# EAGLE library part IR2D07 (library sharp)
16.bit LED panel driver Source: http://document.sharpsma.com/files/IR2D07.pdf
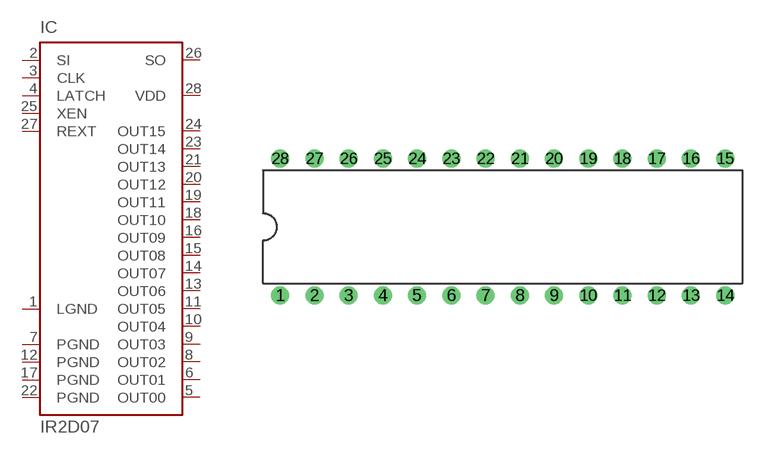
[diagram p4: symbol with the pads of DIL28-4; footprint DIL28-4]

Designator prefix IC

## IR2D07 (OC_FARNELL: unknown; OC_NEWARK: unknown)  [DIL28-4]
1  LGND  pwr
2  SI  in
3  CLK  in
4  LATCH  in
5  OUT00  out
6  OUT01  out
7  PGND  pwr
8  OUT02  out
9  OUT03  out
10  OUT04  out
11  OUT05  out
12  PGND  pwr
13  OUT06  out
14  OUT07  out
15  OUT08  out
16  OUT09  out
17  PGND  pwr
18  OUT10  out
19  OUT11  out
20  OUT12  out
21  OUT13  out
22  PGND  pwr
23  OUT14  out
24  OUT15  out
25  XEN  in
26  SO  out
27  REXT  in
28  VDD  pwr

## Footprint DIL28-4 (pad centres in mm)
Dual In Line Package
drill 0.813 round: 1 -16.51,-5.08; 2 -13.97,-5.08; 3 -11.43,-5.08; 4 -8.89,-5.08; 5 -6.35,-5.08; 6 -3.81,-5.08; 7 -1.27,-5.08; 8 1.27,-5.08; 9 3.81,-5.08; 10 6.35,-5.08; 11 8.89,-5.08; 12 11.43,-5.08; 13 13.97,-5.08; 14 16.51,-5.08; 15 16.51,5.08; 16 13.97,5.08; 17 11.43,5.08; 18 8.89,5.08; 19 6.35,5.08; 20 3.81,5.08; 21 1.27,5.08; 22 -1.27,5.08; 23 -3.81,5.08; 24 -6.35,5.08; 25 -8.89,5.08; 26 -11.43,5.08; 27 -13.97,5.08; 28 -16.51,5.08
